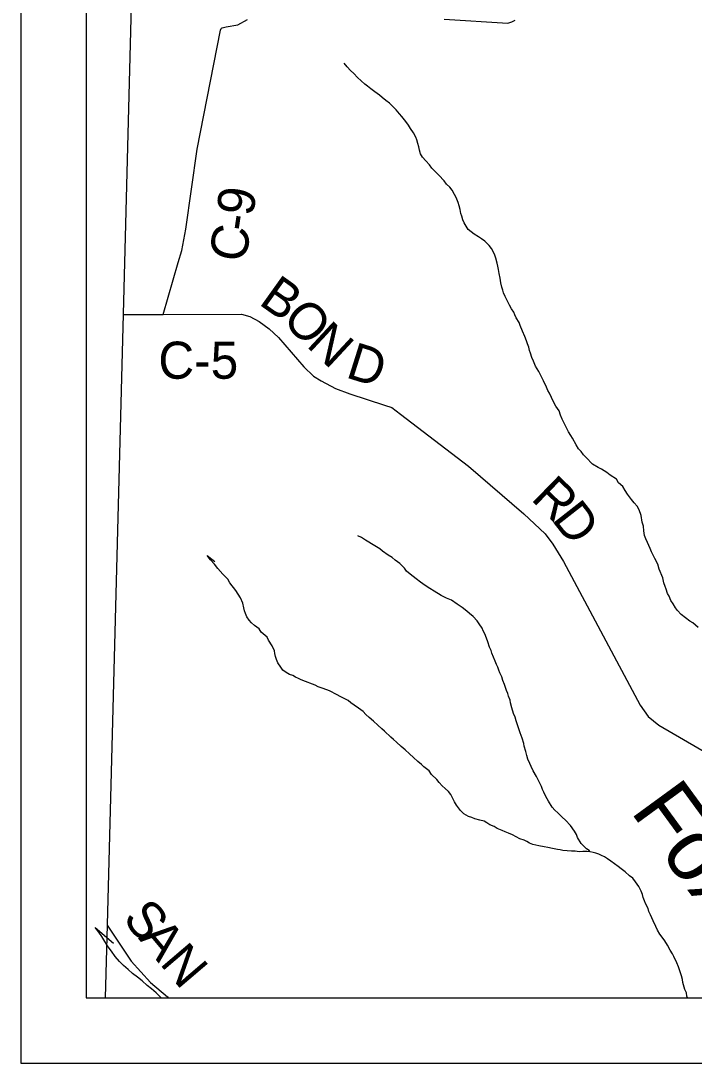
# Model space of a CAD drawing. Extents: x -7.5 to 26.5, y 3.5 to 25.5.
# Drawn here: x -5.457 to -4.425, y 17.5 to 19.097 of the extents above; entities that cross this region are included whole.
import ezdxf

# ---------------------------------------------------------------- set-up
doc = ezdxf.new("R2010")
doc.units = 0
for name, color, linetype in [('GM_X_Corporation', 7, 'Continuous'), ('GM_X_County_Road', 7, 'Continuous'), ('GM_X_County_Road_Text', 7, 'Continuous'), ('GM_X_Minor_River', 7, 'Continuous'), ('GM_X_Minor_River_Text', 7, 'Continuous'), ('SH_Data', 7, 'Continuous')]:
    doc.layers.add(name, color=color, linetype=linetype)

msp = doc.modelspace()

# ---------------------------------------------------------------- linework, layer by layer
at = {"layer": 'GM_X_Corporation'}
for points in [[(-5.2848, 19.2392), (-5.3003, 18.6476), (-5.3247, 17.7117), (-5.3276, 17.6), (1.4431, 17.6), (1.4431, 24.4)], [(-5.2848, 19.2392), (-5.3003, 18.6476), (-5.3247, 17.7117), (-5.3276, 17.6), (-2.0482, 17.6)]]:
    msp.add_lwpolyline(points, dxfattribs=at)
at = {"layer": 'GM_X_County_Road'}
for points in [[(-4.8082, 19.0995), (-4.7109, 19.0936), (-4.7048, 19.0953), (-4.6997, 19.0982)], [(-5.239, 18.6472), (-5.2157, 18.7265), (-5.2102, 18.7449), (-5.2041, 18.7777), (-5.187, 18.9005), (-5.1509, 19.0829), (-5.15, 19.0851), (-5.1494, 19.0858), (-5.1485, 19.0863), (-5.1423, 19.0876), (-5.1244, 19.0908), (-5.1097, 19.099)], [(-5.3001, 18.6471), (-5.239, 18.6472), (-5.1191, 18.6474), (-5.1063, 18.6439), (-5.0918, 18.6362), (-5.0766, 18.6251), (-5.0623, 18.6117), (-5.0232, 18.5668), (-5.0085, 18.5526), (-4.997, 18.5454), (-4.975, 18.5337), (-4.9529, 18.5257), (-4.9001, 18.508), (-4.8884, 18.5046), (-4.8751, 18.4943), (-4.7713, 18.4145), (-4.6865, 18.3415), (-4.6538, 18.3112), (-4.6422, 18.2952), (-4.6257, 18.2688), (-4.508, 18.0486), (-4.4961, 18.0312), (-4.4798, 18.0177), (-4.382, 17.9609)], [(-5.3245, 17.7112), (-5.2878, 17.6564), (-5.2582, 17.6235), (-5.2324, 17.6014), (-5.2311, 17.6)]]:
    msp.add_lwpolyline(points, dxfattribs=at)
at = {"layer": 'GM_X_Minor_River'}
for points in [[(-4.7855, 18.8134), (-4.7868, 18.8184), (-4.7899, 18.8264), (-4.7924, 18.8311), (-4.796, 18.8373), (-4.8, 18.842), (-4.8048, 18.8467), (-4.8084, 18.8518), (-4.8165, 18.8604), (-4.8231, 18.8671), (-4.8271, 18.8714), (-4.8311, 18.8761), (-4.8366, 18.8824), (-4.8414, 18.8883), (-4.8446, 18.8933), (-4.8463, 18.8987), (-4.8473, 18.9037), (-4.849, 18.909), (-4.8503, 18.9144), (-4.8517, 18.9186), (-4.8552, 18.9256), (-4.86, 18.9322), (-4.8632, 18.9373), (-4.8672, 18.9427), (-4.8734, 18.9502), (-4.8767, 18.9545), (-4.8821, 18.9607), (-4.8869, 18.9655), (-4.8924, 18.9706), (-4.898, 18.975), (-4.9035, 18.9797), (-4.9076, 18.9829), (-4.9146, 18.9881), (-4.9209, 18.9929), (-4.9257, 18.9968), (-4.9301, 19), (-4.9412, 19.0103), (-4.947, 19.0162), (-4.9518, 19.0209), (-4.9573, 19.0264), (-4.9617, 19.0319)], [(-4.464, 18.2156), (-4.4661, 18.2198), (-4.4682, 18.226), (-4.4699, 18.2302), (-4.472, 18.236), (-4.4737, 18.2436), (-4.4793, 18.2568), (-4.4809, 18.2644), (-4.4859, 18.2733), (-4.4888, 18.2791), (-4.4909, 18.2834), (-4.493, 18.2884), (-4.4972, 18.2977), (-4.4993, 18.3034), (-4.5018, 18.3084), (-4.5027, 18.3157), (-4.5032, 18.3226), (-4.5049, 18.3291), (-4.5068, 18.339), (-4.5099, 18.3475), (-4.5128, 18.3533), (-4.5175, 18.3584), (-4.5215, 18.3638), (-4.5277, 18.3717), (-4.5313, 18.3775), (-4.5349, 18.3837), (-4.5412, 18.3892), (-4.5444, 18.3947), (-4.5544, 18.4011), (-4.5592, 18.4047), (-4.5674, 18.4103), (-4.5726, 18.4124), (-4.5812, 18.4176), (-4.5907, 18.4278), (-4.5951, 18.4321), (-4.5987, 18.4372), (-4.6028, 18.4411), (-4.6064, 18.4473), (-4.6121, 18.4574), (-4.6146, 18.4617), (-4.6182, 18.4675), (-4.6214, 18.4745), (-4.6249, 18.4814), (-4.6278, 18.4868), (-4.6302, 18.4926), (-4.6323, 18.4995), (-4.6373, 18.5065), (-4.6402, 18.512), (-4.6441, 18.5197), (-4.6473, 18.5263), (-4.6494, 18.5305), (-4.6519, 18.5359), (-4.6565, 18.5456), (-4.6611, 18.5545), (-4.6636, 18.5599), (-4.6683, 18.568), (-4.6718, 18.5754), (-4.6743, 18.5812), (-4.6763, 18.5877), (-4.6777, 18.5919), (-4.679, 18.5969), (-4.6808, 18.6019), (-4.6821, 18.6065), (-4.6849, 18.6134), (-4.6884, 18.6215), (-4.6919, 18.63), (-4.6937, 18.6346), (-4.698, 18.642), (-4.7001, 18.6463), (-4.7019, 18.6505), (-4.7055, 18.6556), (-4.7083, 18.6614), (-4.7108, 18.6664), (-4.7151, 18.6745), (-4.7175, 18.6803), (-4.7185, 18.6845), (-4.7199, 18.6888), (-4.7216, 18.6953), (-4.7228, 18.7029), (-4.7241, 18.7098), (-4.725, 18.7159), (-4.7264, 18.7209), (-4.7274, 18.7259), (-4.7294, 18.7335), (-4.7307, 18.7378), (-4.7336, 18.7436), (-4.7361, 18.7482), (-4.7393, 18.7525), (-4.7463, 18.7592), (-4.7515, 18.7632), (-4.756, 18.766), (-4.7623, 18.77), (-4.7671, 18.7736), (-4.7719, 18.7772), (-4.7748, 18.7822), (-4.7776, 18.7876), (-4.7797, 18.7923), (-4.7815, 18.7977), (-4.7828, 18.8019), (-4.7841, 18.808), (-4.7855, 18.8134)], [(-4.5847, 17.8238), (-4.5864, 17.8258), (-4.5905, 17.8282), (-4.5945, 17.8322), (-4.5985, 17.8365), (-4.6043, 17.8458), (-4.6056, 17.8504), (-4.6089, 17.8555), (-4.6147, 17.864), (-4.6227, 17.8723), (-4.6275, 17.877), (-4.6345, 17.8837), (-4.6389, 17.8876), (-4.6429, 17.8923), (-4.6487, 17.9013), (-4.6526, 17.9086), (-4.6558, 17.9152), (-4.6579, 17.9195), (-4.6593, 17.9241), (-4.6636, 17.9322), (-4.6671, 17.9392), (-4.6721, 17.9481), (-4.6753, 17.9543), (-4.6771, 17.9589), (-4.6803, 17.9658), (-4.6816, 17.9716), (-4.6833, 17.9773), (-4.6857, 17.9858), (-4.6863, 17.99), (-4.689, 17.9977), (-4.6922, 18.0061), (-4.6935, 18.0107), (-4.6984, 18.0246), (-4.6997, 18.0299), (-4.7022, 18.0357), (-4.7049, 18.0442), (-4.7069, 18.0518), (-4.7075, 18.056), (-4.71, 18.0622), (-4.711, 18.0664), (-4.7131, 18.0711), (-4.7162, 18.0799), (-4.7187, 18.0861), (-4.72, 18.0918), (-4.7232, 18.098), (-4.7249, 18.1022), (-4.7263, 18.1065), (-4.7281, 18.1107), (-4.7302, 18.1157), (-4.733, 18.1219), (-4.7354, 18.1281), (-4.7364, 18.1323), (-4.7389, 18.1373), (-4.7417, 18.1454), (-4.7437, 18.1511), (-4.7462, 18.1577), (-4.7487, 18.1623), (-4.7504, 18.1666), (-4.7548, 18.1732), (-4.758, 18.1775), (-4.7642, 18.1845), (-4.7698, 18.1889), (-4.7738, 18.1925), (-4.7809, 18.198), (-4.7883, 18.2032), (-4.7972, 18.2092), (-4.805, 18.2125), (-4.8129, 18.2166), (-4.824, 18.2231), (-4.8304, 18.2271), (-4.8378, 18.2319), (-4.8445, 18.2367), (-4.8515, 18.2419), (-4.8607, 18.2494), (-4.8659, 18.2538), (-4.8691, 18.2584), (-4.8765, 18.2655), (-4.8835, 18.2707), (-4.8879, 18.2747), (-4.8943, 18.2783), (-4.9028, 18.2843), (-4.9068, 18.2882), (-4.9121, 18.2911), (-4.9199, 18.2959), (-4.924, 18.298), (-4.9288, 18.3015), (-4.9351, 18.3052), (-4.9407, 18.3077)], [(-4.9626, 18.0592), (-4.9678, 18.062), (-4.9726, 18.0644), (-4.9842, 18.0702), (-4.9883, 18.0718), (-4.9951, 18.0747), (-5.0014, 18.0768), (-5.0059, 18.0789), (-5.0104, 18.0806), (-5.0209, 18.0847), (-5.0273, 18.0872), (-5.0314, 18.0893), (-5.0363, 18.0913), (-5.0403, 18.0938), (-5.0452, 18.0954), (-5.0504, 18.0983), (-5.0556, 18.1023), (-5.0589, 18.1066), (-5.0632, 18.1132), (-5.0653, 18.1182), (-5.0667, 18.1228), (-5.0677, 18.1274), (-5.0683, 18.1316), (-5.0718, 18.1393), (-5.0776, 18.1482), (-5.0797, 18.1529), (-5.0886, 18.1604), (-5.0918, 18.1654), (-5.0988, 18.1706), (-5.1036, 18.1746), (-5.1073, 18.1789), (-5.1105, 18.1836), (-5.1126, 18.189), (-5.1144, 18.1932), (-5.1154, 18.1978), (-5.117, 18.2047), (-5.1205, 18.2128), (-5.1241, 18.2186), (-5.1277, 18.2244), (-5.1368, 18.2361), (-5.1397, 18.2416), (-5.1474, 18.249), (-5.1554, 18.2577), (-5.1605, 18.2643), (-5.1664, 18.2714), (-5.1714, 18.278), (-5.1596, 18.2688)], [(-4.4193, 18.1677), (-4.4274, 18.1748), (-4.4323, 18.1772), (-4.4389, 18.1824), (-4.4452, 18.1872), (-4.4511, 18.1935), (-4.454, 18.1977), (-4.4576, 18.2039), (-4.4612, 18.2086), (-4.464, 18.2156)], [(-4.4568, 17.6633), (-4.4585, 17.6675), (-4.4621, 17.6733), (-4.4664, 17.6807), (-4.4704, 17.6873), (-4.4744, 17.6928), (-4.478, 17.6978), (-4.4816, 17.7036), (-4.4844, 17.7094), (-4.4883, 17.7179), (-4.4901, 17.7225), (-4.4926, 17.7272), (-4.4947, 17.7322), (-4.496, 17.7368), (-4.4999, 17.7445), (-4.5017, 17.7488), (-4.5034, 17.7538), (-4.5048, 17.7584), (-4.5065, 17.7634), (-4.5104, 17.7707), (-4.5155, 17.7778), (-4.5195, 17.7832), (-4.5247, 17.7872), (-4.5313, 17.7931), (-4.5372, 17.7979), (-4.542, 17.8015), (-4.5531, 17.8095), (-4.558, 17.813), (-4.5628, 17.8159), (-4.5673, 17.8183), (-4.5714, 17.82), (-4.5759, 17.8216), (-4.5804, 17.8229), (-4.5849, 17.8238), (-4.5898, 17.8244), (-4.5959, 17.8242), (-4.6016, 17.824), (-4.608, 17.8246), (-4.6134, 17.8248), (-4.6202, 17.8254), (-4.6266, 17.826), (-4.6308, 17.8266), (-4.6349, 17.8275), (-4.6425, 17.8289), (-4.6496, 17.8306), (-4.6553, 17.8316), (-4.6636, 17.833), (-4.6681, 17.8339), (-4.6726, 17.8352), (-4.6778, 17.8373), (-4.682, 17.8394), (-4.686, 17.8418), (-4.6924, 17.8439), (-4.704, 17.85), (-4.71, 17.8525), (-4.7148, 17.8546), (-4.7197, 17.8562), (-4.7272, 17.8595), (-4.7316, 17.8627), (-4.7384, 17.8652), (-4.7432, 17.8681), (-4.7473, 17.8705), (-4.7537, 17.8722), (-4.7616, 17.8744), (-4.7661, 17.8765), (-4.7714, 17.8778), (-4.7784, 17.8822), (-4.7836, 17.8873), (-4.7894, 17.8951), (-4.7926, 17.9002), (-4.7951, 17.9056), (-4.7983, 17.9114), (-4.802, 17.9161), (-4.8067, 17.9208), (-4.8115, 17.9251), (-4.8163, 17.9302), (-4.8195, 17.9345), (-4.828, 17.942), (-4.8316, 17.9479), (-4.8394, 17.9538), (-4.8434, 17.9574), (-4.8486, 17.9621), (-4.8552, 17.9681), (-4.8615, 17.974), (-4.8681, 17.9799), (-4.8744, 17.9851), (-4.8817, 17.9918), (-4.8862, 17.9957), (-4.8902, 17.9997), (-4.8998, 18.0084), (-4.9038, 18.0123), (-4.9101, 18.0178), (-4.9167, 18.0238), (-4.9233, 18.0297), (-4.9285, 18.0344), (-4.9325, 18.0387), (-4.9399, 18.0439), (-4.9462, 18.0487), (-4.9514, 18.0523), (-4.9555, 18.0555), (-4.9626, 18.0592)], [(-5.2421, 17.6), (-5.2426, 17.6004), (-5.2495, 17.6075), (-5.2569, 17.6138), (-5.2632, 17.6189), (-5.2709, 17.6261), (-5.2783, 17.6316), (-5.2861, 17.6376), (-5.2927, 17.6435), (-5.2997, 17.6498), (-5.306, 17.6558), (-5.3122, 17.6632), (-5.318, 17.6714), (-5.323, 17.6784), (-5.3281, 17.6865), (-5.3331, 17.6939), (-5.3375, 17.7005), (-5.3429, 17.7079), (-5.3149, 17.6838)], [(-4.4356, 17.6), (-4.4365, 17.6025), (-4.4374, 17.6079), (-4.4399, 17.6129), (-4.4426, 17.6237), (-4.4432, 17.6282), (-4.4449, 17.6336), (-4.4473, 17.6413), (-4.4494, 17.6478), (-4.4522, 17.6536), (-4.4568, 17.6633)]]:
    msp.add_lwpolyline(points, dxfattribs=at)
at = {"layer": 'SH_Data'}
for p, q in [((-5.4569, 24.5), (-5.4569, 17.5)), ((-5.3569, 24.4), (-5.3569, 17.6)), ((-5.3569, 17.6), (1.4431, 17.6)), ((-5.3569, 17.6), (-5.3569, 17.6)), ((-5.4569, 17.5), (1.5431, 17.5))]:
    msp.add_line(p, q, dxfattribs=at)

# ---------------------------------------------------------------- texts
at = {"layer": 'GM_X_County_Road_Text'}
for s, height, rotation, p in [('9', 0.0568, 81.8232, (-5.1014, 18.7962)), ('-', 0.0568, 81.3848, (-5.105, 18.7726)), ('C', 0.0568, 79.7148, (-5.1136, 18.7249)), ('B', 0.0568, 324.4887, (-5.0942, 18.6638)), ('O', 0.0568, 312.9797, (-5.0584, 18.6387)), ('N', 0.0568, 317.102, (-5.0212, 18.599)), ('C-5', 0.05682, 0, (-5.2463, 18.5486)), ('D', 0.0568, 342.494, (-4.961, 18.5512)), ('R', 0.0568, 315.7427, (-4.6771, 18.3639)), ('D', 0.0568, 308.0601, (-4.645, 18.3328)), ('S', 0.0568, 309.8041, (-5.3025, 17.7208)), ('A', 0.0568, 309.8157, (-5.2779, 17.6914)), ('N', 0.0568, 310.4775, (-5.2454, 17.6524))]:
    msp.add_text(s, height=height, rotation=rotation, dxfattribs=at).set_placement(p)
at = {"layer": 'GM_X_Minor_River_Text'}
msp.add_text('Fox', height=0.09469, rotation=306.1544, dxfattribs=at).set_placement((-4.5244, 17.8863))

doc.saveas('drawing.dxf')
